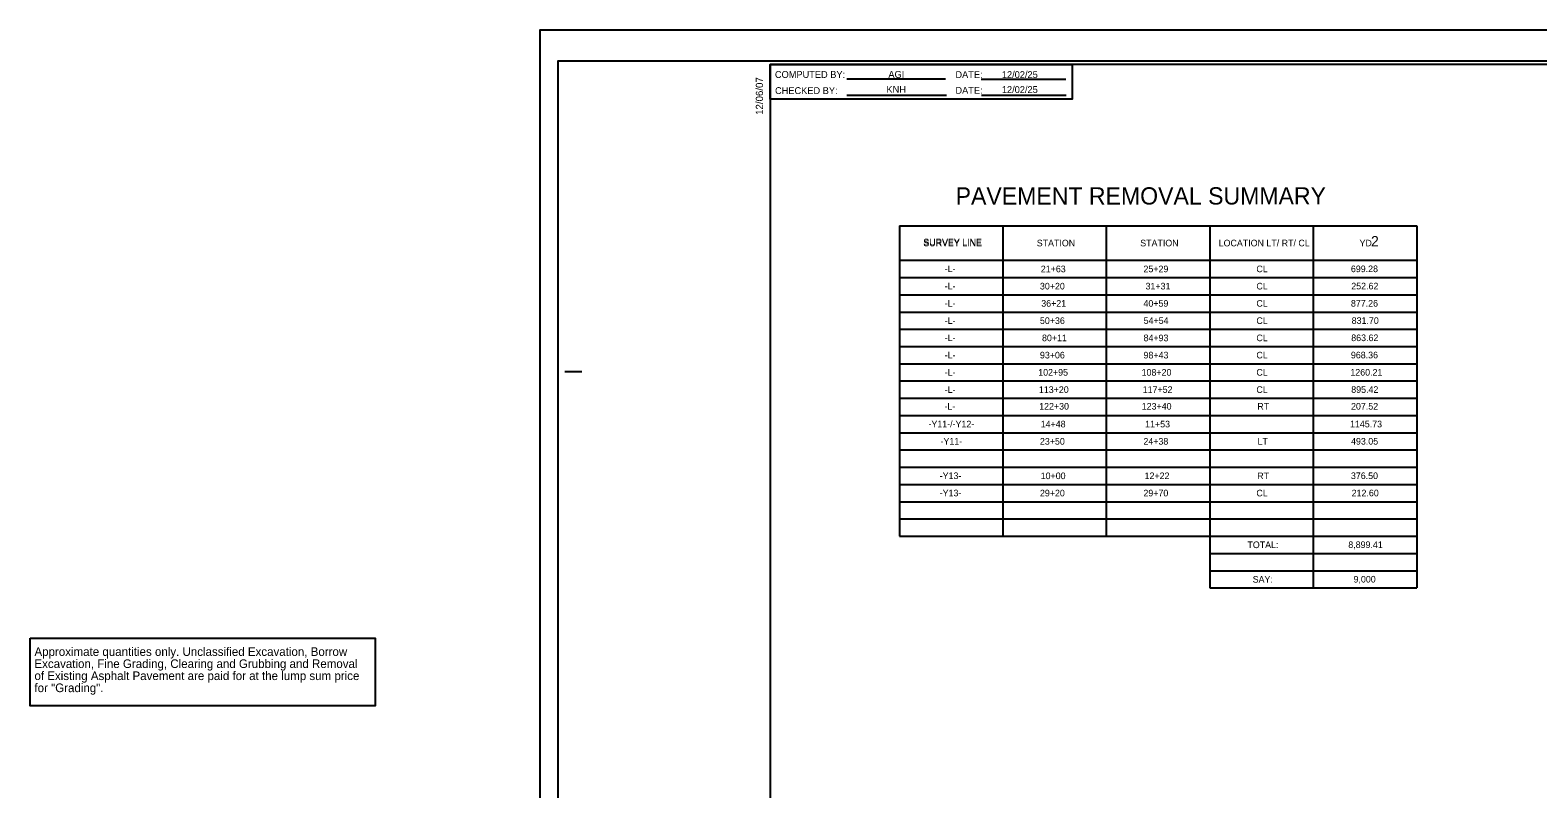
# Model space of a CAD drawing. Extents: x 1729984.8 to 1730033.5, y 539934.2 to 539956.2.
# Drawn here: x 1729984.82 to 1730006.67, y 539945.17 to 539956.17 of the extents above; entities that cross this region are included whole.
import ezdxf

# ---------------------------------------------------------------- set-up
doc = ezdxf.new("R2010")
doc.units = 0
for name, color, linetype in [('Sheet Cutting Line CELL', 7, 'Continuous'), ('Sheet Data Field CELL', 7, 'Continuous'), ('Sheet Plot Border Inside CELL', 7, 'Continuous'), ('Sheet Plot Border Outside CELL', 7, 'Continuous'), ('Sheet Summary Combination CELL', 7, 'Continuous'), ('Sheet Summary Combination Grid CELL', 7, 'Continuous'), ('Sheet Summary Earthwork CELL', 7, 'Continuous')]:
    doc.layers.add(name, color=color, linetype=linetype)

msp = doc.modelspace()

# ---------------------------------------------------------------- linework, layer by layer
at = {"layer": 'Sheet Cutting Line CELL'}
for p, q in [((1730025.883, 539956.171), (1729992.203, 539956.171)), ((1729992.203, 539956.171), (1729992.203, 539934.171))]:
    msp.add_line(p, q, dxfattribs=at)
at = {"layer": 'Sheet Plot Border Inside CELL'}
msp.add_lwpolyline([(1730025.793, 539955.722), (1729992.463, 539955.722), (1729992.463, 539934.62), (1730025.793, 539934.62)], close=True, dxfattribs=at)
at = {"layer": 'Sheet Plot Border Outside CELL'}
msp.add_lwpolyline([(1730025.883, 539956.171), (1729992.203, 539956.171), (1729992.203, 539934.171), (1730025.883, 539934.171)], close=True, dxfattribs=at)
at = {"layer": 'Sheet Summary Combination CELL'}
for p, q in [((1729996.656, 539955.463), (1729998.087, 539955.463)), ((1729998.603, 539955.46), (1729999.831, 539955.46)), ((1729996.656, 539955.229), (1729998.101, 539955.229)), ((1729998.606, 539955.23), (1729999.834, 539955.23)), ((1730001.179, 539953.333), (1730001.179, 539953.333)), ((1730001.304, 539953.331), (1730001.304, 539953.331)), ((1730001.485, 539953.335), (1730001.485, 539953.335)), ((1730001.597, 539953.333), (1730001.597, 539953.333)), ((1729992.565, 539951.221), (1729992.815, 539951.221))]:
    msp.add_line(p, q, dxfattribs=at)
for points in [[(1730025.543, 539955.671), (1729995.543, 539955.671), (1729995.543, 539934.671), (1730025.543, 539934.671)], [(1729995.543, 539955.671), (1729999.923, 539955.671), (1729999.923, 539955.171), (1729995.543, 539955.171)]]:
    msp.add_lwpolyline(points, close=True, dxfattribs=at)
at = {"layer": 'Sheet Summary Combination Grid CELL'}
for p, q in [((1729997.416, 539953.334), (1730004.919, 539953.334)), ((1729997.416, 539953.334), (1729997.416, 539948.834)), ((1729998.916, 539953.334), (1729998.916, 539948.834)), ((1730000.416, 539953.334), (1730000.416, 539948.834)), ((1730001.916, 539953.334), (1730001.916, 539948.084)), ((1730003.416, 539953.334), (1730003.416, 539948.084)), ((1730004.919, 539953.334), (1730004.919, 539948.084)), ((1729997.416, 539952.834), (1730004.919, 539952.834)), ((1729997.416, 539952.584), (1730004.919, 539952.584)), ((1729997.416, 539952.334), (1730004.919, 539952.334)), ((1729997.416, 539952.084), (1730004.919, 539952.084)), ((1729997.416, 539951.834), (1730004.919, 539951.834)), ((1729997.416, 539951.584), (1730004.919, 539951.584)), ((1729997.416, 539951.334), (1730004.919, 539951.334)), ((1729997.416, 539951.084), (1730004.919, 539951.084)), ((1729997.416, 539950.834), (1730004.919, 539950.834)), ((1729997.416, 539950.584), (1730004.919, 539950.584)), ((1729997.416, 539950.334), (1730004.919, 539950.334)), ((1729997.416, 539950.084), (1730004.919, 539950.084)), ((1729997.416, 539949.834), (1730004.919, 539949.834)), ((1729997.416, 539949.584), (1730004.919, 539949.584)), ((1729997.416, 539949.334), (1730004.919, 539949.334)), ((1729997.416, 539949.084), (1730004.919, 539949.084)), ((1729997.416, 539948.834), (1730004.919, 539948.834)), ((1730001.916, 539948.584), (1730004.919, 539948.584)), ((1730001.916, 539948.334), (1730004.919, 539948.334)), ((1730001.916, 539948.084), (1730004.919, 539948.084))]:
    msp.add_line(p, q, dxfattribs=at)
at = {"layer": 'Sheet Summary Earthwork CELL'}
msp.add_lwpolyline([(1729984.816, 539947.353), (1729989.817, 539947.353), (1729989.817, 539946.372), (1729984.816, 539946.372)], close=True, dxfattribs=at)

# ---------------------------------------------------------------- texts
at = {"layer": 'Sheet Data Field CELL'}
for s, height, p in [('AGI', 0.1, (1729997.257, 539955.479)), ('12/02/25', 0.1, (1729998.902, 539955.476)), ('KNH', 0.1, (1729997.229, 539955.262)), ('12/02/25', 0.1, (1729998.902, 539955.259)), ('-L-', 0.096, (1729998.07, 539950.669)), ('122+30', 0.096, (1729999.443, 539950.669)), ('123+40', 0.096, (1730000.93, 539950.669)), ('RT', 0.096, (1730002.605, 539950.669)), ('207.52', 0.096, (1730003.964, 539950.669))]:
    msp.add_text(s, height=height, dxfattribs=at).set_placement(p)
at = {"layer": 'Sheet Summary Combination CELL'}
for s, height, rotation, p in [('12/06/07', 0.105, 90, (1729995.44, 539954.942)), ('PAVEMENT REMOVAL SUMMARY', 0.25, 0.0119, (1729998.232, 539953.642))]:
    msp.add_text(s, height=height, rotation=rotation, dxfattribs=at).set_placement(p)
for s, height, p in [('COMPUTED BY:', 0.1, (1729995.612, 539955.478)), ('DATE:', 0.1, (1729998.229, 539955.476)), ('CHECKED BY:', 0.1, (1729995.614, 539955.244)), ('DATE:', 0.1, (1729998.229, 539955.248)), ('SURVEY LINE', 0.096, (1729997.764, 539953.051)), ('SURVEY LINE', 0.096, (1729997.764, 539953.036)), ('STATION', 0.096, (1729999.408, 539953.036)), ('STATION', 0.096, (1730000.908, 539953.036)), ('LOCATION LT/ RT/ CL', 0.096, (1730002.045, 539953.036)), ('-L-', 0.096, (1729998.073, 539952.662)), ('21+63', 0.096, (1729999.467, 539952.661)), ('25+29', 0.096, (1730000.955, 539952.661)), ('CL', 0.096, (1730002.592, 539952.661)), ('699.28', 0.096, (1730003.962, 539952.662)), ('-L-', 0.096, (1729998.073, 539952.412)), ('30+20', 0.096, (1729999.454, 539952.411)), ('31+31', 0.096, (1730000.985, 539952.411)), ('CL', 0.096, (1730002.592, 539952.411)), ('252.62', 0.096, (1730003.967, 539952.412)), ('-L-', 0.096, (1729998.073, 539952.162)), ('36+21', 0.096, (1729999.473, 539952.161)), ('40+59', 0.096, (1730000.955, 539952.161)), ('CL', 0.096, (1730002.592, 539952.161)), ('877.26', 0.096, (1730003.962, 539952.162)), ('-L-', 0.096, (1729998.073, 539951.912)), ('50+36', 0.096, (1729999.454, 539951.911)), ('54+54', 0.096, (1730000.957, 539951.911)), ('CL', 0.096, (1730002.592, 539951.911)), ('831.70', 0.096, (1730003.973, 539951.912)), ('-L-', 0.096, (1729998.073, 539951.662)), ('80+11', 0.096, (1729999.484, 539951.661)), ('84+93', 0.096, (1730000.956, 539951.661)), ('CL', 0.096, (1730002.592, 539951.661)), ('863.62', 0.096, (1730003.967, 539951.662)), ('-L-', 0.096, (1729998.073, 539951.412)), ('93+06', 0.096, (1729999.454, 539951.411)), ('98+43', 0.096, (1730000.956, 539951.411)), ('CL', 0.096, (1730002.592, 539951.411)), ('968.36', 0.096, (1730003.962, 539951.412)), ('-L-', 0.096, (1729998.073, 539951.162)), ('102+95', 0.096, (1729999.429, 539951.161)), ('108+20', 0.096, (1730000.928, 539951.161)), ('CL', 0.096, (1730002.592, 539951.161)), ('1260.21', 0.096, (1730003.954, 539951.162)), ('-L-', 0.096, (1729998.073, 539950.912)), ('113+20', 0.096, (1729999.439, 539950.911)), ('117+52', 0.096, (1730000.944, 539950.911)), ('CL', 0.096, (1730002.592, 539950.911)), ('895.42', 0.096, (1730003.967, 539950.912)), ('-Y11-/-Y12-', 0.096, (1729997.838, 539950.412)), ('14+48', 0.096, (1729999.465, 539950.411)), ('11+53', 0.096, (1730000.979, 539950.411)), ('1145.73', 0.096, (1730003.949, 539950.412)), ('-Y11-', 0.096, (1729998.013, 539950.162)), ('23+50', 0.096, (1729999.454, 539950.161)), ('24+38', 0.096, (1730000.954, 539950.161)), ('LT', 0.096, (1730002.609, 539950.161)), ('493.05', 0.096, (1730003.964, 539950.162)), ('-Y13-', 0.096, (1729998.001, 539949.662)), ('10+00', 0.096, (1729999.465, 539949.661)), ('12+22', 0.096, (1730000.971, 539949.661)), ('RT', 0.096, (1730002.604, 539949.661)), ('376.50', 0.096, (1730003.962, 539949.662)), ('-Y13-', 0.096, (1729998.001, 539949.412)), ('29+20', 0.096, (1729999.454, 539949.411)), ('29+70', 0.096, (1730000.954, 539949.411)), ('CL', 0.096, (1730002.592, 539949.411)), ('212.60', 0.096, (1730003.973, 539949.412)), ('TOTAL:', 0.096, (1730002.462, 539948.661)), ('8,899.41', 0.096, (1730003.924, 539948.662)), ('SAY:', 0.096, (1730002.538, 539948.161)), ('9,000', 0.096, (1730004, 539948.162))]:
    msp.add_text(s, height=height, dxfattribs=at).set_placement(p)
at = {"layer": 'Sheet Summary Combination Grid CELL'}
for s, height, p in [('YD', 0.096, (1730004.087, 539953.036)), ('2', 0.15, (1730004.254, 539953.036))]:
    msp.add_text(s, height=height, dxfattribs=at).set_placement(p)
at = {"layer": 'Sheet Summary Earthwork CELL'}
for s, p in [('Approximate quantities only. Unclassified Excavation, Borrow ', (1729984.878, 539947.098)), ('Excavation, Fine Grading, Clearing and Grubbing and Removal ', (1729984.878, 539946.923)), ('for "Grading".', (1729984.878, 539946.573)), ('of Existing Asphalt Pavement are paid for at the lump sum price', (1729984.878, 539946.748))]:
    msp.add_text(s, height=0.125, dxfattribs=at).set_placement(p)

doc.saveas('drawing.dxf')
